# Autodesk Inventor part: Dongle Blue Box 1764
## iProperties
Created: 2010-01
Part Number: Dongle Blue Box 1764
Document SubType Name: Modeling
Designer: jgehrig
Density: 1 g/cm^3
Author: jgehrig
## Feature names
1. Extrusion1
